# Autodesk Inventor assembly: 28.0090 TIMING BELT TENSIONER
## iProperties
Created: 2007-04
Part Number: 28.0090 TIMING BELT TENSIONER
Document SubType Name: Assembly
Designer: Andy Moles
Author: Andy Moles
